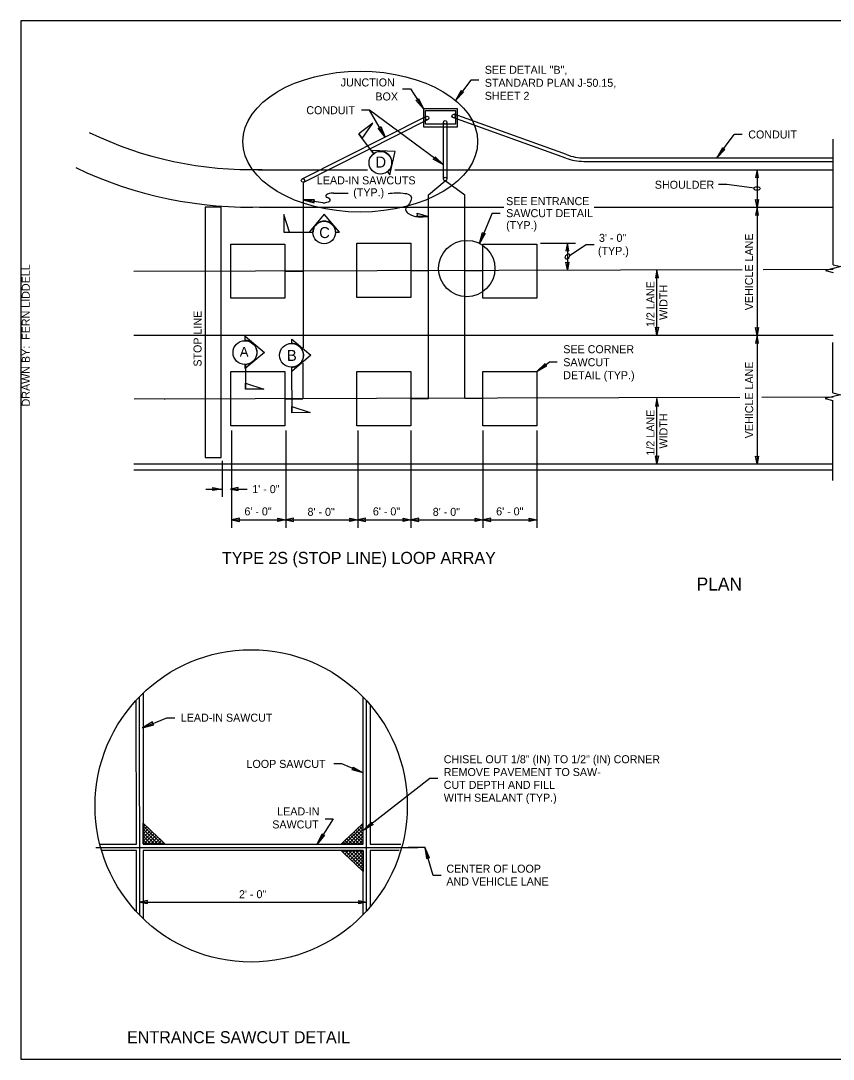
# Model space of a CAD drawing. Extents: x 99862 to 103680, y 99470 to 102076.
# Drawn here: x 99862 to 101487, y 100000 to 102076 of the extents above; entities that cross this region are included whole.
import ezdxf

# ---------------------------------------------------------------- set-up
doc = ezdxf.new("R2010")
doc.units = 0
for name, color, linetype in [('Level 1', 7, 'Continuous'), ('Level 14', 7, 'Continuous'), ('Level 15', 7, 'Continuous'), ('Level 18', 7, 'Continuous'), ('Level 20', 7, 'Continuous'), ('Level 22', 7, 'Continuous'), ('Level 27', 7, 'Continuous'), ('Level 60', 7, 'Continuous'), ('Level 62', 7, 'Continuous'), ('Level 9', 7, 'Continuous')]:
    doc.layers.add(name, color=color, linetype=linetype)

msp = doc.modelspace()

# ---------------------------------------------------------------- linework, layer by layer
at = {"layer": 'Level 1'}
msp.add_lwpolyline([(99862, 99999.5), (103151, 99999.5), (103151, 102075.5), (99862, 102075.5)], close=True, dxfattribs=at)
at = {"layer": 'Level 14'}
msp.add_lwpolyline([(100677.1, 101684.5), (100654.1, 101684.8), (100655.5, 101687.6), (100654.9, 101690.7)], close=True, dxfattribs=at)
at = {"layer": 'Level 15'}
for p, q in [((100559.6, 101896.7), (100543.6, 101896.7)), ((100707, 101787.3), (100559.6, 101896.7)), ((100590.8, 101842.5), (100559.6, 101896.7)), ((101253.6, 101801.7), (101288.7, 101848.2)), ((101304.7, 101848.2), (101288.7, 101848.2)), ((101486.6, 101587.9), (101486.6, 101839)), ((100487.3, 101731), (100516.5, 101731)), ((100465.7, 101711.6), (100426.6, 101717.7)), ((100804.6, 101690.9), (100779.4, 101630.3)), ((100804.6, 101690.9), (100820.6, 101690.9)), ((100959.2, 101606.1), (100992.7, 101628.4)), ((100992.7, 101628.4), (101008.7, 101628.4)), ((101485.8, 101331.7), (101485.8, 101432)), ((100894.2, 101374.1), (100918.8, 101392.9)), ((100934.8, 101392.9), (100918.8, 101392.9)), ((101485.8, 101156.7), (101485.8, 101316.2)), ((100264.5, 101196), (100264.5, 101123.9)), ((100231.8, 101139.2), (100263.9, 101139.2)), ((100283.4, 101139.2), (100314.9, 101139.2)), ((100100, 100286.9), (100099.6, 100724)), ((100553.6, 100295.8), (100553.6, 100716.1)), ((100012.2, 100423.1), (100656.1, 100423.1)), ((100636.6, 100423.4), (100669.9, 100423.4))]:
    msp.add_line(p, q, dxfattribs=at)
for points in [[(100777.9, 101956.5), (100762.1, 101956.5), (100731.1, 101916.4)], [(100625.4, 101939.2), (100641.1, 101939.2), (100667.1, 101899.4)], [(101334.3, 101777.8), (101334.3, 101702.7)], [(101328.5, 101741), (101273.7, 101748.5), (101257.5, 101748.5)], [(101334.3, 101702.7), (101334.3, 101446.7)], [(100901.3, 101631.2), (100971, 101631.2)], [(100955, 101631.2), (100955, 101577.3)], [(101486.6, 101587.9), (101502.1, 101584), (101471.1, 101576.3), (101486.6, 101572.4)], [(101134, 101447.3), (101134, 101577.6)], [(101334.3, 101446.7), (101334.3, 101189.7)], [(101485.8, 101331.7), (101501.3, 101327.8), (101470.3, 101320.1), (101485.8, 101316.2)], [(101134, 101190.3), (101134, 101320.5)], [(100283.4, 101256.2), (100283.4, 101061.8)], [(100391.8, 101256.2), (100391.8, 101061.8)], [(100535.8, 101256.2), (100535.8, 101061.8)], [(100642.2, 101256.2), (100642.2, 101061.8)], [(100786.2, 101256.2), (100786.2, 101061.8)], [(100894.2, 101256.2), (100894.2, 101061.8)], [(100283.4, 101077.8), (100391.8, 101077.8)], [(100391.8, 101077.8), (100535.8, 101077.8)], [(100535.8, 101077.8), (100642.2, 101077.8)], [(100642.2, 101077.8), (100786.2, 101077.8)], [(100786.2, 101077.8), (100894.2, 101077.8)], [(100105.7, 100662.2), (100154, 100682.3), (100170, 100682.3)], [(100546.9, 100572.1), (100504.2, 100589.9), (100488.2, 100589.9)], [(100695.8, 100560.8), (100679.8, 100560.8), (100546.9, 100456.8)], [(100470.8, 100480.2), (100486.8, 100480.2), (100454.8, 100429.4)], [(100702.7, 100366.6), (100686.7, 100366.6), (100669.9, 100423.4)], [(100100, 100313.4), (100553.6, 100313.4)]]:
    msp.add_lwpolyline(points, dxfattribs=at)
for points in [[(100731.1, 101916.4), (100747.4, 101932.6), (100744.4, 101933.6), (100742.7, 101936.3)], [(100667.1, 101899.4), (100652.1, 101916.9), (100655.2, 101917.7), (100657.1, 101920.2)], [(100590.8, 101842.5), (100576.8, 101860.8), (100579.9, 101861.4), (100582, 101863.8)], [(101253.6, 101801.7), (101269.8, 101818.1), (101266.7, 101819.1), (101265, 101821.7)], [(100707, 101787.3), (100686.9, 101798.5), (100689.6, 101800.3), (100690.5, 101803.3)], [(101334.3, 101777.8), (101331.2, 101762.1), (101334.3, 101762.8), (101337.4, 101762.1)], [(100426.6, 101717.7), (100448.7, 101711.4), (100448.1, 101714.5), (100449.6, 101717.3)], [(101334.3, 101702.7), (101331.2, 101718.5), (101334.3, 101717.7), (101337.4, 101718.5)], [(101334.3, 101702.7), (101331.2, 101687), (101334.3, 101687.7), (101337.4, 101687)], [(100779.4, 101630.3), (100785.4, 101652.5), (100787.8, 101650.4), (100790.9, 101650.2)], [(100955, 101631.2), (100952, 101615.4), (100955, 101616.2), (100958.1, 101615.4)], [(100955, 101577.3), (100952, 101593), (100955, 101592.3), (100958.1, 101593)], [(101134, 101577.6), (101130.9, 101561.9), (101134, 101562.6), (101137.1, 101561.9)], [(101134, 101447.3), (101130.9, 101463.1), (101134, 101462.3), (101137.1, 101463.1)], [(101334.3, 101446.7), (101331.2, 101462.4), (101334.3, 101461.7), (101337.4, 101462.4)], [(101334.3, 101446.7), (101331.2, 101430.9), (101334.3, 101431.7), (101337.4, 101430.9)], [(100894.2, 101374.1), (100914.1, 101385.6), (100911.5, 101387.3), (100910.5, 101390.3)], [(101134, 101320.5), (101130.9, 101304.8), (101134, 101305.5), (101137.1, 101304.8)], [(101134, 101190.3), (101130.9, 101206), (101134, 101205.3), (101137.1, 101206)], [(101334.3, 101189.7), (101331.2, 101205.4), (101334.3, 101204.7), (101337.4, 101205.4)], [(100283.4, 101077.8), (100299.1, 101074.7), (100298.4, 101077.8), (100299.1, 101080.9)], [(100391.8, 101077.8), (100376.1, 101074.7), (100376.8, 101077.8), (100376.1, 101080.9)], [(100391.8, 101077.8), (100407.5, 101074.7), (100406.8, 101077.8), (100407.5, 101080.9)], [(100535.8, 101077.8), (100520.1, 101074.7), (100520.8, 101077.8), (100520.1, 101080.9)], [(100535.8, 101077.8), (100551.5, 101074.7), (100550.8, 101077.8), (100551.5, 101080.9)], [(100642.2, 101077.8), (100626.4, 101074.7), (100627.2, 101077.8), (100626.4, 101080.9)], [(100642.2, 101077.8), (100657.9, 101074.7), (100657.2, 101077.8), (100657.9, 101080.9)], [(100786.2, 101077.8), (100770.5, 101074.7), (100771.2, 101077.8), (100770.5, 101080.9)], [(100786.2, 101077.8), (100801.9, 101074.7), (100801.2, 101077.8), (100801.9, 101080.9)], [(100894.2, 101077.8), (100878.4, 101074.7), (100879.2, 101077.8), (100878.4, 101080.9)], [(100105.7, 100662.2), (100127.9, 100668.2), (100125.8, 100670.6), (100125.6, 100673.7)], [(100546.9, 100572.1), (100524.7, 100578.1), (100526.8, 100580.5), (100527, 100583.6)], [(100546.9, 100456.8), (100563.1, 100473.2), (100564.1, 100470.2), (100566.7, 100468.5)], [(100454.8, 100429.4), (100464.4, 100450.3), (100466.4, 100447.8), (100469.5, 100447.1)], [(100669.9, 100423.4), (100673.5, 100400.7), (100676.1, 100402.5), (100679.2, 100402.4)], [(100100, 100313.8), (100115.7, 100310.7), (100115, 100313.8), (100115.7, 100316.9)], [(100553.6, 100313.4), (100537.8, 100310.3), (100538.6, 100313.4), (100537.8, 100316.5)]]:
    msp.add_lwpolyline(points, close=True, dxfattribs=at)
msp.add_circle((100322.7, 100506), 312.2, dxfattribs=at)
for centre, major_axis, ratio in [((100540.9, 101833.9), (-234.7, 0), 0.6), ((101334.3, 101740.3), (6, 0), 0.57735), ((100955, 101604.2), (3, 5.2), 0.57735)]:
    msp.add_ellipse(centre, major_axis=major_axis, ratio=ratio, dxfattribs=at)
for centre, start_param, end_param in [((100487.2, 101725.4), 4.705244, 7.068624), ((100465.7, 101717.3), 1.570796, 3.926959)]:
    msp.add_ellipse(centre, major_axis=(-15.2, 0), ratio=0.375, start_param=start_param, end_param=end_param, dxfattribs=at)
msp.add_spline([(100596.7, 101730.5), (100630.2, 101730.5), (100641.6, 101725.8), (100642.3, 101716), (100631.7, 101696.1), (100637.1, 101690.4), (100677.1, 101684.5)], degree=3, dxfattribs=at)
at = {"layer": 'Level 18'}
for p, q in [((100424.9, 101759.4), (100673.5, 101884.5)), ((100427.7, 101752.9), (100676.1, 101877.9)), ((100706.9, 101872.3), (100706.9, 101759.5)), ((100713.9, 101872.3), (100713.9, 101759.5)), ((100952, 101801), (100726.1, 101882.1)), ((100953.3, 101808), (100728.7, 101888.5)), ((100088.2, 101189.7), (101486.6, 101189.7)), ((100088.2, 101177.5), (101486.6, 101177.5)), ((100106.6, 100730.9), (100106.7, 100720)), ((100093.2, 100429.4), (100093, 100717)), ((100106.7, 100720), (100106.8, 100429.4)), ((100546.9, 100429.4), (100546.9, 100723.2)), ((100560.6, 100708.2), (100560.6, 100429.4)), ((100020.1, 100429.4), (100093.2, 100429.4)), ((100093.2, 100416.7), (100023.6, 100416.7)), ((100093.3, 100294), (100093.2, 100416.7)), ((100106.8, 100429.4), (100330.4, 100429.4)), ((100317.4, 100416.7), (100106.8, 100416.7)), ((100106.8, 100416.7), (100106.9, 100280.1)), ((100546.9, 100416.7), (100317.4, 100416.7)), ((100330.4, 100429.4), (100546.9, 100429.4)), ((100546.9, 100288.8), (100546.9, 100416.7)), ((100560.6, 100429.4), (100621.8, 100429.4)), ((100618.9, 100416.7), (100560.6, 100416.7)), ((100560.6, 100416.7), (100560.6, 100303.8)), ((100546.9, 100288.8), (100546.9, 100374.8))]:
    msp.add_line(p, q, dxfattribs=at)
for points in [[(100261.8, 101139.2), (100246.1, 101136.2), (100246.8, 101139.2), (100246.1, 101142.3)], [(100281.3, 101139.2), (100297, 101136.2), (100296.3, 101139.2), (100297, 101142.3)], [(100150, 100429.8), (100106.8, 100429.8), (100106.8, 100471.7), (100150.3, 100430.4)], [(100503.8, 100429.8), (100546.9, 100429.8), (100546.9, 100471.7), (100503.4, 100430.4)], [(100503.8, 100416.7), (100546.9, 100416.7), (100546.9, 100374.8), (100503.4, 100416)]]:
    msp.add_lwpolyline(points, close=True, dxfattribs=at)
for centre in [(100674.7, 101881), (100710.6, 101872.3), (100727.5, 101885.1), (100426.5, 101756.2), (100710.6, 101759.2)]:
    msp.add_circle(centre, 3.5, dxfattribs=at)
at = {"layer": 'Level 20'}
for p, q in [((100987.8, 101794.4), (101486.6, 101794.4)), ((100989.1, 101801.4), (101486.6, 101801.4)), ((101346.5, 101578.4), (101486.6, 101578.8)), ((100087.9, 101574.7), (101304.2, 101578.3)), ((100088.2, 101446.7), (100304.9, 101446.7)), ((100304.9, 101446.7), (101486.6, 101446.7)), ((100088.6, 101319.5), (101299.6, 101323)), ((100148.6, 101319.6), (100151, 101319.6)), ((101344.1, 101323.1), (101486.6, 101323.5)), ((100181.7, 101189.7), (100197.8, 101189.7))]:
    msp.add_line(p, q, dxfattribs=at)
for points in [[(100336.6, 101777.8), (100555.3, 101777.8)], [(100609.8, 101777.8), (101486.6, 101777.8)], [(100230.8, 101202.5), (100262.4, 101202.5), (100262.4, 101702.7), (100230.8, 101702.7), (100230.8, 101202.5)], [(100339.6, 101702.7), (100827.8, 101702.7)], [(101008.8, 101702.7), (101486.6, 101702.7)]]:
    msp.add_lwpolyline(points, dxfattribs=at)
for radius, start, end in [(736, 244.0268, 271.8119), (811.1, 244.4957, 272.0506)]:
    msp.add_arc((100321.4, 102513.9), radius, start, end, dxfattribs=at)
at = {"layer": 'Level 22'}
for p, q in [((100677.5, 101727.7), (100710.6, 101755.7)), ((100750.2, 101726.6), (100710.6, 101755.7)), ((100390.2, 101574.9), (100426.5, 101574.9)), ((100642.1, 101576.2), (100677.5, 101576.2)), ((100750.2, 101576.2), (100786.2, 101576.2)), ((100390.2, 101319.8), (100426.2, 101319.8)), ((100641.5, 101320.7), (100677.5, 101320.7)), ((100750.2, 101321), (100786.2, 101321))]:
    msp.add_line(p, q, dxfattribs=at)
for points in [[(100667.1, 101863.7), (100735.2, 101863.7), (100735.2, 101899.4), (100667.1, 101899.4), (100667.1, 101863.7)], [(100426.7, 101752.7), (100426.7, 101421.5)], [(100677.5, 101320.7), (100677.5, 101727.7)], [(100750.2, 101321.5), (100750.2, 101726.6)], [(100426.3, 101391.2), (100426.2, 101319.8)]]:
    msp.add_lwpolyline(points, dxfattribs=at)
for points in [[(100671.3, 101896), (100731.2, 101896), (100731.2, 101868.8), (100671.3, 101868.8)], [(100282.2, 101629.2), (100390.2, 101629.2), (100390.2, 101520.7), (100282.2, 101520.7)], [(100534.2, 101631.2), (100642.2, 101631.2), (100642.2, 101522.6), (100534.2, 101522.6)], [(100786.2, 101629.2), (100894.2, 101629.2), (100894.2, 101520.7), (100786.2, 101520.7)], [(100282.2, 101374.1), (100390.2, 101374.1), (100390.2, 101265.6), (100282.2, 101265.6)], [(100534.2, 101374.1), (100642.2, 101374.1), (100642.2, 101265.6), (100534.2, 101265.6)], [(100786.2, 101374.1), (100894.2, 101374.1), (100894.2, 101265.6), (100786.2, 101265.6)]]:
    msp.add_lwpolyline(points, close=True, dxfattribs=at)
at = {"layer": 'Level 27'}
for p, q in [((100106.8, 100471), (100107.3, 100471.5)), ((100106.8, 100463.9), (100110.9, 100468.1)), ((100106.8, 100466.4), (100143.4, 100429.8)), ((100106.8, 100456.9), (100114.6, 100464.6)), ((100106.8, 100449.8), (100118.2, 100461.2)), ((100106.8, 100459.3), (100136.4, 100429.8)), ((100106.8, 100442.7), (100121.8, 100457.7)), ((100546.9, 100466.4), (100510.3, 100429.8)), ((100546.9, 100459.3), (100517.4, 100429.8)), ((100546.9, 100442.7), (100531.9, 100457.7)), ((100546.9, 100449.8), (100535.6, 100461.2)), ((100546.9, 100456.9), (100539.2, 100464.6)), ((100546.9, 100463.9), (100542.8, 100468.1)), ((100546.9, 100471), (100546.4, 100471.5)), ((100106.8, 100435.6), (100125.4, 100454.2)), ((100106.8, 100452.3), (100129.3, 100429.8)), ((100106.8, 100445.2), (100122.2, 100429.8)), ((100106.8, 100438.1), (100115.2, 100429.8)), ((100108, 100429.8), (100129, 100450.8)), ((100115.1, 100429.8), (100132.6, 100447.3)), ((100122.1, 100429.8), (100136.3, 100443.9)), ((100129.2, 100429.8), (100139.9, 100440.4)), ((100136.3, 100429.8), (100143.5, 100437)), ((100139.5, 100440.8), (100150.2, 100430.1)), ((100514.3, 100440.8), (100503.6, 100430.1)), ((100517.5, 100429.8), (100510.3, 100437)), ((100524.5, 100429.8), (100513.9, 100440.4)), ((100531.6, 100429.8), (100517.5, 100443.9)), ((100538.7, 100429.8), (100521.1, 100447.3)), ((100546.9, 100452.3), (100524.4, 100429.8)), ((100545.7, 100429.8), (100524.7, 100450.8)), ((100546.9, 100435.6), (100528.3, 100454.2)), ((100546.9, 100445.2), (100531.5, 100429.8)), ((100546.9, 100438.1), (100538.6, 100429.8)), ((100106.8, 100431), (100108.1, 100429.8)), ((100143.3, 100429.8), (100147.1, 100433.5)), ((100514.3, 100405.7), (100503.6, 100416.4)), ((100510.4, 100429.8), (100506.6, 100433.5)), ((100510.4, 100416.7), (100506.6, 100413)), ((100517.5, 100416.7), (100510.3, 100409.5)), ((100546.9, 100380.1), (100510.3, 100416.7)), ((100524.5, 100416.7), (100513.9, 100406.1)), ((100546.9, 100387.2), (100517.4, 100416.7)), ((100531.6, 100416.7), (100517.5, 100402.6)), ((100538.7, 100416.7), (100521.1, 100399.1)), ((100546.9, 100394.2), (100524.4, 100416.7)), ((100545.7, 100416.7), (100524.7, 100395.7)), ((100546.9, 100401.3), (100531.5, 100416.7)), ((100546.9, 100408.4), (100538.6, 100416.7)), ((100546.9, 100431), (100545.7, 100429.8)), ((100546.9, 100415.4), (100545.7, 100416.7)), ((100546.9, 100410.8), (100528.3, 100392.2)), ((100546.9, 100403.8), (100531.9, 100388.8)), ((100546.9, 100396.7), (100535.6, 100385.3)), ((100546.9, 100389.6), (100539.2, 100381.9)), ((100546.9, 100382.5), (100542.8, 100378.4)), ((100546.9, 100375.5), (100546.4, 100374.9))]:
    msp.add_line(p, q, dxfattribs=at)
for centre in [(100989.1, 101901.4), (100987.8, 101894.4)]:
    msp.add_arc(centre, 100, 248.9916, 270, dxfattribs=at)
at = {"layer": 'Level 60'}
msp.add_line((99862, 99999.5), (99862, 99999.5), dxfattribs=at)
at = {"layer": 'Level 9'}
for p, q in [((100567.6, 101810), (100537.7, 101849.5)), ((100563.2, 101816.2), (100568, 101809.8)), ((100610.8, 101813.9), (100563.2, 101816.2)), ((100600.2, 101767.4), (100610.8, 101813.9)), ((100595.3, 101773.8), (100600.2, 101767.4)), ((100469, 101689.1), (100438.4, 101652.6)), ((100499.6, 101652.6), (100469, 101689.1)), ((100446, 101652.4), (100387.8, 101652.4)), ((100438.4, 101652.6), (100446.4, 101652.6)), ((100491.6, 101652.6), (100499.6, 101652.6)), ((100311, 101436.3), (100311, 101444.7)), ((100311, 101444.7), (100349.4, 101412.6)), ((100403.7, 101430.4), (100403.7, 101438.8)), ((100403.7, 101438.8), (100442.1, 101406.8)), ((100349.4, 101412.6), (100311, 101380.4)), ((100442.1, 101406.8), (100403.8, 101374.5)), ((100311, 101380.4), (100311, 101388.8)), ((100311.1, 101388.6), (100311.1, 101338.8)), ((100403.5, 101382.9), (100403.8, 101292)), ((100403.8, 101374.5), (100403.8, 101382.9))]:
    msp.add_line(p, q, dxfattribs=at)
for points in [[(100544.7, 101840.2), (100565.8, 101870.9), (100537.7, 101849.5)], [(100399.4, 101652.6), (100387.7, 101687.9), (100387.7, 101652.6)], [(100311.1, 101351.1), (100348.3, 101338.8), (100311.1, 101338.8)], [(100403.7, 101304.3), (100440.9, 101292.1), (100403.8, 101292)]]:
    msp.add_lwpolyline(points, close=True, dxfattribs=at)
for centre, radius in [((100581.1, 101791.7), 22.6), ((100468.7, 101652.1), 22.6), ((100468.7, 101652.1), 22.6), ((100753.8, 101580.1), 56.3), ((100310.2, 101412.1), 23.8), ((100403.4, 101406.7), 23.8)]:
    msp.add_circle(centre, radius, dxfattribs=at)
for centre, radius, start, end in [((100581.7, 101791.8), 22.6, 307.1863, 127.1907), ((100469, 101652.6), 22.6, 359.9978, 180.0022), ((100311, 101412.6), 23.8, 269.9978, 90.0022), ((100403.7, 101406.7), 23.8, 270.1524, 90.1569)]:
    msp.add_arc(centre, radius, start, end, dxfattribs=at)

# ---------------------------------------------------------------- texts
at = {"layer": 'Level 15'}
for s, p in [('LEAD-IN SAWCUTS ', (100454.1, 101748.5)), ('(TYP.)', (100526.8, 101724.5))]:
    msp.add_text(s, height=16, dxfattribs=at).set_placement(p)
at = {"layer": 'Level 20'}
for s, rotation, p in [('SEE DETAIL "B",', 360, (100789.9, 101969.5)), ('JUNCTION ', 360, (100501.7, 101944.2)), ('STANDARD PLAN J-50.15,', 360, (100789.9, 101943.5)), ('BOX', 360, (100571.1, 101916.2)), ('SHEET 2 ', 360, (100789.9, 101917.5)), ('SHOULDER', 360, (101129.9, 101739.7)), ('SEE ENTRANCE', 360, (100832.6, 101706.9)), ('SAWCUT DETAIL', 360, (100832.6, 101682.9)), ('(TYP.)', 360, (100832.6, 101658.9)), ('3\' - 0"', 360, (101018.2, 101633.5)), ('VEHICLE LANE', 90, (101326.2, 101496.8)), ('(TYP.)', 360, (101016.1, 101607.5)), ('1/2 LANE', 90, (101129.2, 101463.3)), (' WIDTH', 90, (101155.2, 101471.5)), ('STOP LINE', 90, (100223.5, 101384.1)), ('VEHICLE LANE', 90, (101326.5, 101240.9)), ('1/2 LANE', 90, (101129.2, 101206.3)), (' WIDTH', 90, (101155.2, 101214.4)), ('LOOP SAWCUT', 360, (100313.4, 100581.9))]:
    msp.add_text(s, height=16, rotation=rotation, dxfattribs=at).set_placement(p)
for s, height, p in [('CONDUIT', 16, (100432.9, 101888.7)), ('CONDUIT', 16, (101316.7, 101840.2)), ('SEE CORNER ', 16, (100946.8, 101410.9)), ('SAWCUT ', 16, (100946.8, 101384.9)), ('DETAIL (TYP.)', 16, (100946.8, 101358.9)), ('1\' - 0"', 16, (100324.9, 101131.2)), ('6\' - 0"', 16, (100309.2, 101086.7)), ('8\' - 0"', 16, (100435.4, 101085.8)), ('6\' - 0"', 16, (100566.1, 101086.7)), ('8\' - 0"', 16, (100685.8, 101085.8)), ('6\' - 0"', 16, (100812.6, 101086.7)), ('TYPE 2S (STOP LINE) LOOP ARRAY', 24, (100264.4, 100989.8)), ('PLAN', 26, (101213.4, 100936.5)), ('LEAD-IN SAWCUT', 16, (100182, 100674.3)), ('CHISEL OUT 1/8" (IN) TO 1/2" (IN) CORNER', 16, (100707.8, 100591.2)), ('REMOVE PAVEMENT TO SAW-', 16, (100707.8, 100565.6)), ('CUT DEPTH AND FILL ', 16, (100707.8, 100540)), ('WITH SEALANT (TYP.)', 16, (100707.8, 100514.4)), ('LEAD-IN', 16, (100374.8, 100486.9)), ('SAWCUT', 16, (100364.9, 100460.9)), ('CENTER OF LOOP', 16, (100713.1, 100372.4)), ('AND VEHICLE LANE', 16, (100713.1, 100346.8)), ('2\' - 0"', 16, (100298.4, 100321.4)), ('ENTRANCE SAWCUT DETAIL', 24, (100074.7, 100031.6))]:
    msp.add_text(s, height=height, dxfattribs=at).set_placement(p)
at = {"layer": 'Level 62'}
msp.add_text('DRAWN BY:  FERN LIDDELL', height=16, rotation=90, dxfattribs=at).set_placement((99880, 101304.5))
at = {"layer": 'Level 9'}
for s, p in [('D', (100571.3, 101782)), ('C', (100458.7, 101641.1))]:
    msp.add_text(s, height=22, dxfattribs=at).set_placement(p)
for s, height, rotation, p in [('A', 19.8, 360, (100299.8, 101403.8)), ('B', 22, 0.7196, (100394.3, 101395.3))]:
    msp.add_text(s, height=height, rotation=rotation, dxfattribs=at).set_placement(p)

doc.saveas('drawing.dxf')
